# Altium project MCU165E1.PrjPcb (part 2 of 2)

## Sheet MCU165E1_XDS110_MCU.SchDoc
size 431 x 279 mm; Date: Not shown in title block; ApprovedBy: Not shown in title block; CheckedBy: Not shown in title block; Author: Not shown in title block; CompanyName: Not shown in title block; Engineer: Not shown in title block; Organization: Not shown in title block; Address1: Not shown in title block; Address2: Not shown in title block; Address3: Not shown in title block; Address4: Not shown in title block; DocumentNumber: 8; Revision: Use project parameter SCH_Rev; SheetNumber: 8; SheetTotal: 10; PageSetup: Record=PageOptions¦CenterHorizontal=True¦CenterVertical=True¦PrintScale=1.00¦XCorrection=1.00¦YCorrection=1.00¦PrintKind=0¦BorderSize=5000000¦LeftOffset=0¦BottomOffset=0¦Orientation=2¦PaperLength=1000¦PaperWidth=1000¦Scale=100¦PaperSource=15¦PrintQuality=600¦MediaType=1¦DitherType=10¦PaperKind=Letter¦PrintScaleMode=1
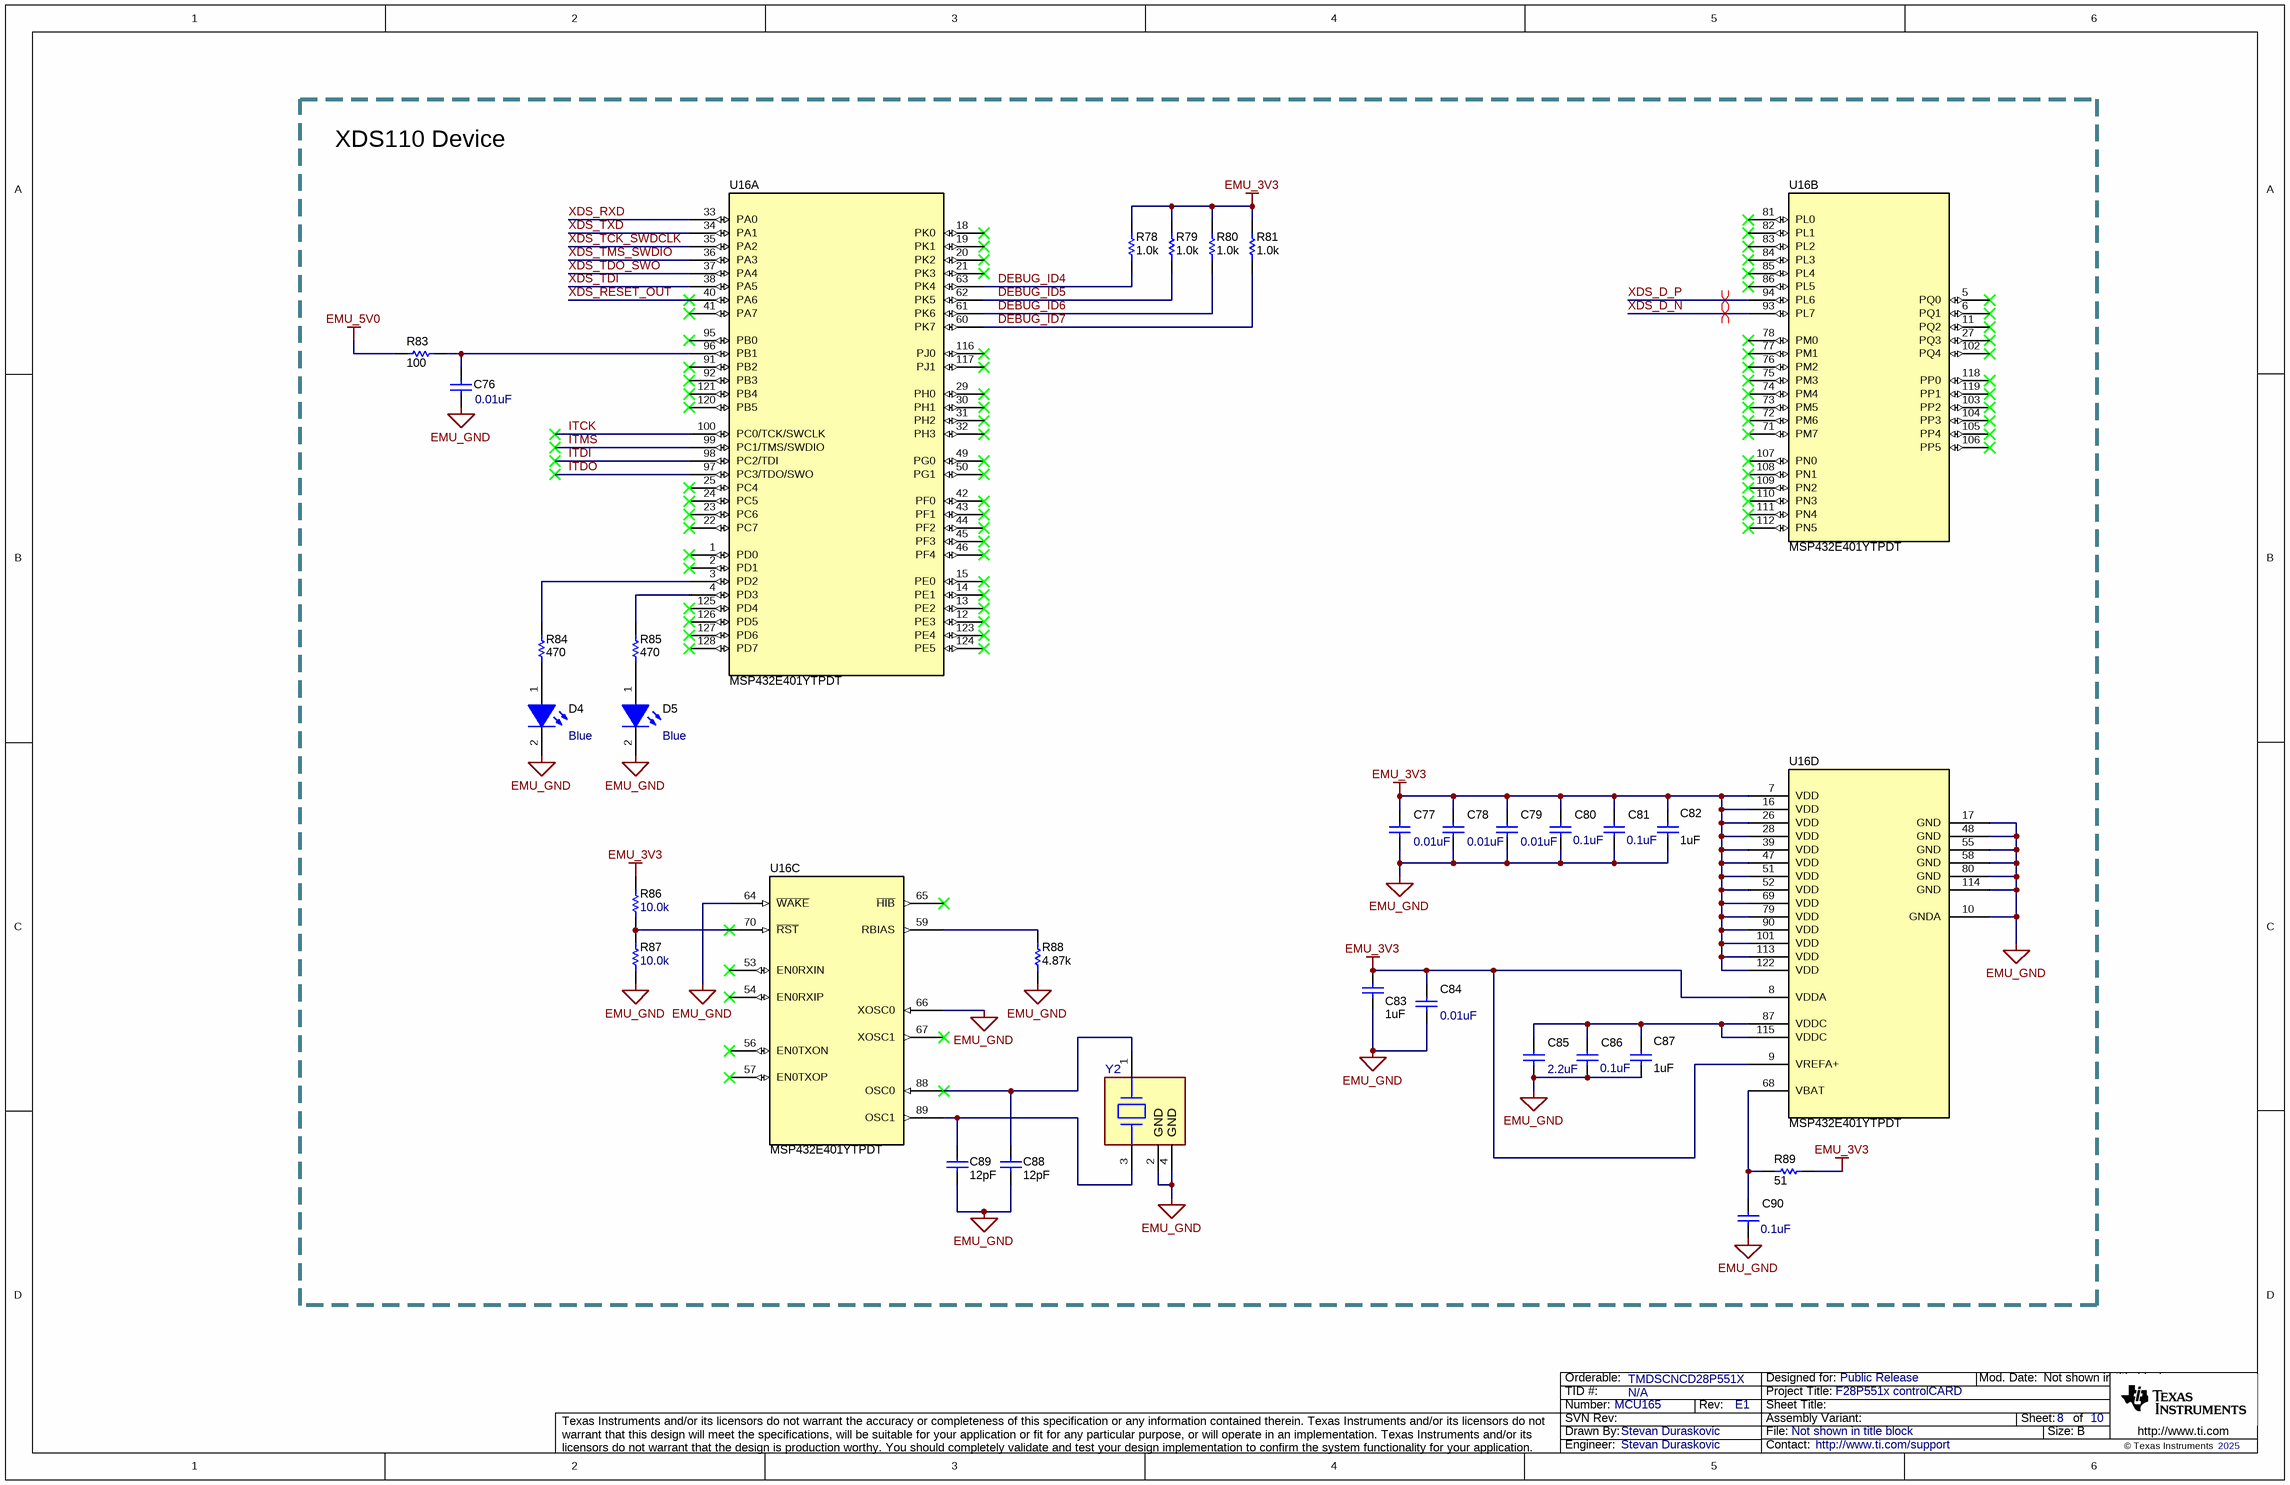
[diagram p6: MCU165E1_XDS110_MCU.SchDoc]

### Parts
C76  ValueDisplayed: 0.01uF  [0402]  (hidden comment: 885012205031)
C77  ValueDisplayed: 0.01uF  [0402]  (hidden comment: 885012205031)
C78  ValueDisplayed: 0.01uF  [0402]  (hidden comment: 885012205031)
C79  ValueDisplayed: 0.01uF  [0402]  (hidden comment: 885012205031)
C80  ValueDisplayed: 0.1uF  [0402]  (hidden comment: 885012205037)
C81  ValueDisplayed: 0.1uF  [0402]  (hidden comment: 885012205037)
C82  ValueDisplayed: 1uF  [0402]  (hidden comment: 885012105012)
C83  ValueDisplayed: 1uF  [0402]  (hidden comment: 885012105012)
C84  ValueDisplayed: 0.01uF  [0402]  (hidden comment: 885012205031)
C85  ValueDisplayed: 2.2uF  [0402]  (hidden comment: 885012105013)
C86  ValueDisplayed: 0.1uF  [0402]  (hidden comment: 885012205037)
C87  ValueDisplayed: 1uF  [0402]  (hidden comment: 885012105012)
C88  ValueDisplayed: 12pF  [0402]  (hidden comment: CL05C120JB5NNNC)
C89  ValueDisplayed: 12pF  [0402]  (hidden comment: CL05C120JB5NNNC)
C90  ValueDisplayed: 0.1uF  [0402]  (hidden comment: 885012205037)
D4  value Blue  [LTST-C170TBKT_Blue]  (hidden comment: LTST-C170TBKT)
D5  value Blue  [LTST-C170TBKT_Blue]  (hidden comment: LTST-C170TBKT)
R78  ValueDisplayed: 1.0k  [0402]  (hidden comment: CRCW04021K00JNED)
R79  ValueDisplayed: 1.0k  [0402]  (hidden comment: CRCW04021K00JNED)
R80  ValueDisplayed: 1.0k  [0402]  (hidden comment: CRCW04021K00JNED)
R81  ValueDisplayed: 1.0k  [0402]  (hidden comment: CRCW04021K00JNED)
R83  ValueDisplayed: 100  [0402]  (hidden comment: CRCW0402100RJNED)
R84  ValueDisplayed: 470  [0402]  (hidden comment: ERJ-2RKF4700X)
R85  ValueDisplayed: 470  [0402]  (hidden comment: ERJ-2RKF4700X)
R86  ValueDisplayed: 10.0k  [0402]  (hidden comment: AC0402FR-0710KL)
R87  ValueDisplayed: 10.0k  [0402]  (hidden comment: AC0402FR-0710KL)
R88  ValueDisplayed: 4.87k  [0402]  (hidden comment: CRCW04024K87FKED)
R89  ValueDisplayed: 51  [0402]  (hidden comment: CRCW040251R0JNED)
U16  MSP432E401YTPDT  [PDT0128A]  (parts A,B,C,D of 4)
Y2  830064296  [FP-830064296_SMT4_3MM4_2MM7-MFG]  (value not drawn)

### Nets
EMU_3V3: C77.1 C78.1 C79.1 C80.1 C81.1 C82.1 C83.1 C84.1 R78.2 R79.2 R80.2 R81.2 R86.2 R89.2 U16.7(VDD) U16.8(VDDA) U16.9(VREFA+) U16.16(VDD) U16.26(VDD) U16.28(VDD) U16.39(VDD) U16.47(VDD) U16.51(VDD) U16.52(VDD) U16.69(VDD) U16.79(VDD) U16.90(VDD) U16.101(VDD) U16.113(VDD) U16.122(VDD)
EMU_5V0: R83.1
EMU_GND: C76.2 C77.2 C78.2 C79.2 C80.2 C81.2 C82.2 C83.2 C84.2 C85.2 C86.2 C87.2 C88.2 C89.2 C90.2 D4.2(K) D5.2(K) R87.1 R88.1 U16.10(GNDA) U16.17(GND) U16.48(GND) U16.55(GND) U16.58(GND) U16.64(~{WAKE}) U16.66(XOSC0) U16.80(GND) U16.114(GND) Y2.2(GND) Y2.4(GND)
DEBUG_ID4: R78.1 U16.63(PK4)
DEBUG_ID5: R79.1 U16.62(PK5)
DEBUG_ID6: R80.1 U16.61(PK6)
DEBUG_ID7: R81.1 U16.60(PK7)
ITCK: U16.100(PC0/TCK/SWCLK)
ITDI: U16.98(PC2/TDI)
ITDO: U16.97(PC3/TDO/SWO)
ITMS: U16.99(PC1/TMS/SWDIO)
XDS_D_N: U16.93(PL7)
XDS_D_P: U16.94(PL6)
XDS_RESET_OUT: U16.40(PA6)
XDS_RXD: U16.33(PA0)
XDS_TCK_SWDCLK: U16.35(PA2)
XDS_TDI: U16.38(PA5)
XDS_TDO_SWO: U16.37(PA4)
XDS_TMS_SWDIO: U16.36(PA3)
XDS_TXD: U16.34(PA1)
NetC76_1: C76.1 R83.2 U16.96(PB1)
NetC85_1: C85.1 C86.1 C87.1 U16.87(VDDC) U16.115(VDDC)
NetC88_1: C88.1 U16.88(OSC0) Y2.1(1_Crystal)
NetC89_1: C89.1 U16.89(OSC1) Y2.3(2_Crystal)
NetC90_1: C90.1 R89.1 U16.68(VBAT)
NetD4_1: D4.1(A) R84.1
NetD5_1: D5.1(A) R85.1
NetR84_2: R84.2 U16.3(PD2)
NetR85_2: R85.2 U16.4(PD3)
NetR86_1: R86.1 R87.2 U16.70(~{RST})
NetR88_2: R88.2 U16.59(RBIAS)

Not connected (* = marked no-connect by the designer): U16 1(PD0)* 2(PD1)* 5(PQ0)* 6(PQ1)* 11(PQ2)* 12(PE3)* 13(PE2)* 14(PE1)* 15(PE0)* 18(PK0)* 19(PK1)* 20(PK2)* 21(PK3)* 22(PC7)* 23(PC6)* 24(PC5)* 25(PC4)* 27(PQ3)* 29(PH0)* 30(PH1)* 31(PH2)* 32(PH3)* 41(PA7)* 42(PF0)* 43(PF1)* 44(PF2)* 45(PF3)* 46(PF4)* 49(PG0)* 50(PG1)* 53(EN0RXIN)* 54(EN0RXIP)* 56(EN0TXON)* 57(EN0TXOP)* 65(~{HIB})* 67(XOSC1)* 71(PM7)* 72(PM6)* 73(PM5)* 74(PM4)* 75(PM3)* 76(PM2)* 77(PM1)* 78(PM0)* 81(PL0)* 82(PL1)* 83(PL2)* 84(PL3)* 85(PL4)* 86(PL5)* 91(PB2)* 92(PB3)* 95(PB0)* 102(PQ4)* 103(PP2)* 104(PP3)* 105(PP4)* 106(PP5)* 107(PN0)* 108(PN1)* 109(PN2)* 110(PN3)* 111(PN4)* 112(PN5)* 116(PJ0)* 117(PJ1)* 118(PP0)* 119(PP1)* 120(PB5)* 121(PB4)* 123(PE4)* 124(PE5)* 125(PD4)* 126(PD5)* 127(PD6)* 128(PD7)*

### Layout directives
differential pair: XDS_D_N, XDS_D_P

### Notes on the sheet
- XDS110 Device

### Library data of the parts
C76-C79 C84 = CMP-0006227-2: CAP, CERM, 0.01 uF, 16 V, +/- 10%, X7R, 0402; Manufacturer: Wurth Elektronik; TaMin_C: -55°C; Polarized: N; SizeAreaWB_mm2: 3; Value1: Unknown; U/M: EA; Value: 0.01uF; TaMax_C: 125°C; SizeZ_mm: 0.6; SizeX_mm: 1; SizeY_mm: 0.5; Value2: 16V; Cap_F: 10nF; AEC Category: Q200
C80 C81 C86 C90 = CMP-0006228-2: CAP, CERM, 0.1 uF, 16 V, +/- 10%, X7R, 0402; Manufacturer: Wurth Elektronik; TaMin_C: -55°C; Polarized: N; SizeAreaWB_mm2: 3; Value1: Unknown; U/M: EA; Value: 0.1uF; TaMax_C: 125°C; SizeZ_mm: 0.6; SizeX_mm: 1; SizeY_mm: 0.5; Value2: 16V; Cap_F: 100nF; AEC Category: Q200
C82 C83 C87 = CMP-0064924-2: CAP, CERM, 1 uF, 10 V,+/- 20%, X5R, 0402; Manufacturer: Wurth Elektronik; TaMin_C: -55°C; Polarized: N; SizeAreaWB_mm2: 3; Value1: Unknown; U/M: EA; Value: 1uF; TaMax_C: 85°C; SizeZ_mm: 0.6; SizeX_mm: 1; SizeY_mm: 0.5; Value2: 10V; Cap_F: 1µF; AEC Category: Q200
C85 = CMP-0006222-2: CAP, CERM, 2.2 uF, 10 V, +/- 20%, X5R, 0402; Manufacturer: Wurth Elektronik; TaMin_C: -55°C; Polarized: N; SizeAreaWB_mm2: 3; Value1: Unknown; U/M: EA; Value: 2.2uF; TaMax_C: 85°C; SizeZ_mm: 0.6; SizeX_mm: 1; SizeY_mm: 0.5; Value2: 10V; Cap_F: 2.2µF; AEC Category: Q200
C88 C89 = CMP-0006345-2: CAP, CERM, 12 pF, 50 V, +/- 5%, C0G/NP0, 0402; Manufacturer: Samsung Electro-Mechanics; Polarized: N; Value: 12pF; U/M: EA; Value1: Unknown; VDC_V: 50V; TaMin_C: -55°C; TaMax_C: 125°C; SizeArea_mm2: 0.5; SizeAreaWB_mm2: 3; SizeX_mm: 1; SizeZ_mm: 0.6; AEC Category: Q200
D4 D5 = CMP-0002889-2: LED, Blue, SMD; Manufacturer: Lite-On; Type: AlInGaP; Vf_V: 3.3V; Io_A: 20mA; Value1: W
R78-R81 = CMP-0026852-3: RES, 1.0 k, 5%, 0.063 W, AEC-Q200 Grade 0, 0402; Manufacturer: Vishay-Dale; Power_W: 63mW; TempCo: 200 ppm/C; Value_Code: 1k00; Value: 1.0k; EIA_Code: E24; Res_ohm: 1k; SizeX_mm: 1; SizeY_mm: 0.5; SizeZ_mm: 0.6; Value2: 0.063W; AEC Qualified: Y; VDC_V: 50V; AEC Category: Q200; AEC Grade: 0
R83 = CMP-0026824-3: RES, 100, 5%, 0.063 W, AEC-Q200 Grade 0, 0402; Manufacturer: Vishay-Dale; Value: 100; Value_Code: 100R; Power_W: 63mW; Value2: 0.063W; VDC_V: 50V; TempCo: 200 ppm/C; SizeArea_mm2: 0.5; SizeX_mm: 1; SizeZ_mm: 0.6; EIA_Code: E24; AEC Category: Q200; AEC Qualified: Y; AEC Grade: 0
R84 R85 = CMP-0026699-1: RES, 470, 1%, 0.1 W, AEC-Q200 Grade 0, 0402; Manufacturer: Panasonic; Value: 470; Value_Code: 470R; Power_W: 100mW; Value2: 0.1W; VDC_V: 50V; TempCo: 100 ppm/C; SizeArea_mm2: 0.5; SizeX_mm: 1; SizeZ_mm: 0.6; U/M: EA; AEC Category: Q200; AEC Qualified: Y; AEC Grade: 0
R86 R87 = CMP-0077731-1: RES, 10.0 k, 1%, 0.063 W, AEC-Q200 Grade 0, 0402; Manufacturer: Yageo America; Power_W: 63mW; TempCo: 100 ppm/C; Value_Code: 10k0; U/M: EA; Value: 10.0k; EIA_Code: E96; Res_ohm: 10k; SizeX_mm: 1.0; SizeY_mm: 0.5; SizeZ_mm: 0.6; Value2: 0.063W; AEC Qualified: Y; VDC_V: 50V; AEC Grade: 0; AEC Category: Q200
R88 = CMP-0026413-2: RES, 4.87 k, 1%, 0.063 W, AEC-Q200 Grade 0, 0402; Manufacturer: Vishay-Dale; Value: 4.87k; Value_Code: 4k87; Power_W: 63mW; Value2: 0.063W; VDC_V: 50V; TempCo: 100 ppm/C; SizeArea_mm2: 0.5; SizeX_mm: 1; SizeZ_mm: 0.6; EIA_Code: E96; AEC Category: Q200; AEC Qualified: Y; AEC Grade: 0
R89 = CMP-0026946-3: RES, 51, 5%, 0.063 W, AEC-Q200 Grade 0, 0402; Manufacturer: Vishay-Dale; Value: 51; Value_Code: 51R0; Power_W: 63mW; Value2: 0.063W; VDC_V: 50V; TempCo: 200 ppm/C; SizeArea_mm2: 0.5; SizeX_mm: 1; SizeZ_mm: 0.6; EIA_Code: E24; AEC Category: Q200; AEC Qualified: Y; AEC Grade: 0
U16 = CMP-0077953-1: MSP432E401YTPDT, PDT0128A (TQFP-128); Alternate PartNumber: MSP432E401YTPDTR; Alternate Manufacturer: Texas Instruments; SizeAreaWB_mm2: 324; SizeZ_mm: 1.2; SizeX_mm: 16; SizeArea_mm2: 256; CompType: IC; AEC Qualified: N; AEC Category: Q200
Y2 = CMP-0094478-1: Crystal 16 MHz ±20ppm Crystal 8pF 70 Ohms 4-SMD, No Lead; Manufacturer: Wurth; SizeZ_mm: 0.8mm; Frequency_Fixed: 16MHz; Esr: 70

## Sheet MCU165E1_Emulator_Interface.SchDoc
size 431 x 279 mm; Date: Not shown in title block; ApprovedBy: Not shown in title block; CheckedBy: Not shown in title block; Author: Not shown in title block; CompanyName: Not shown in title block; Engineer: Not shown in title block; Organization: Not shown in title block; Address1: Not shown in title block; Address2: Not shown in title block; Address3: Not shown in title block; Address4: Not shown in title block; DocumentNumber: 9; Revision: Use project parameter SCH_Rev; SheetNumber: 9; SheetTotal: 10; PageSetup: Record=PageOptions¦CenterHorizontal=True¦CenterVertical=True¦PrintScale=1.00¦XCorrection=1.00¦YCorrection=1.00¦PrintKind=0¦BorderSize=5000000¦LeftOffset=0¦BottomOffset=0¦Orientation=2¦PaperLength=1000¦PaperWidth=1000¦Scale=100¦PaperSource=15¦PrintQuality=600¦MediaType=1¦DitherType=10¦PaperKind=Letter¦PrintScaleMode=1
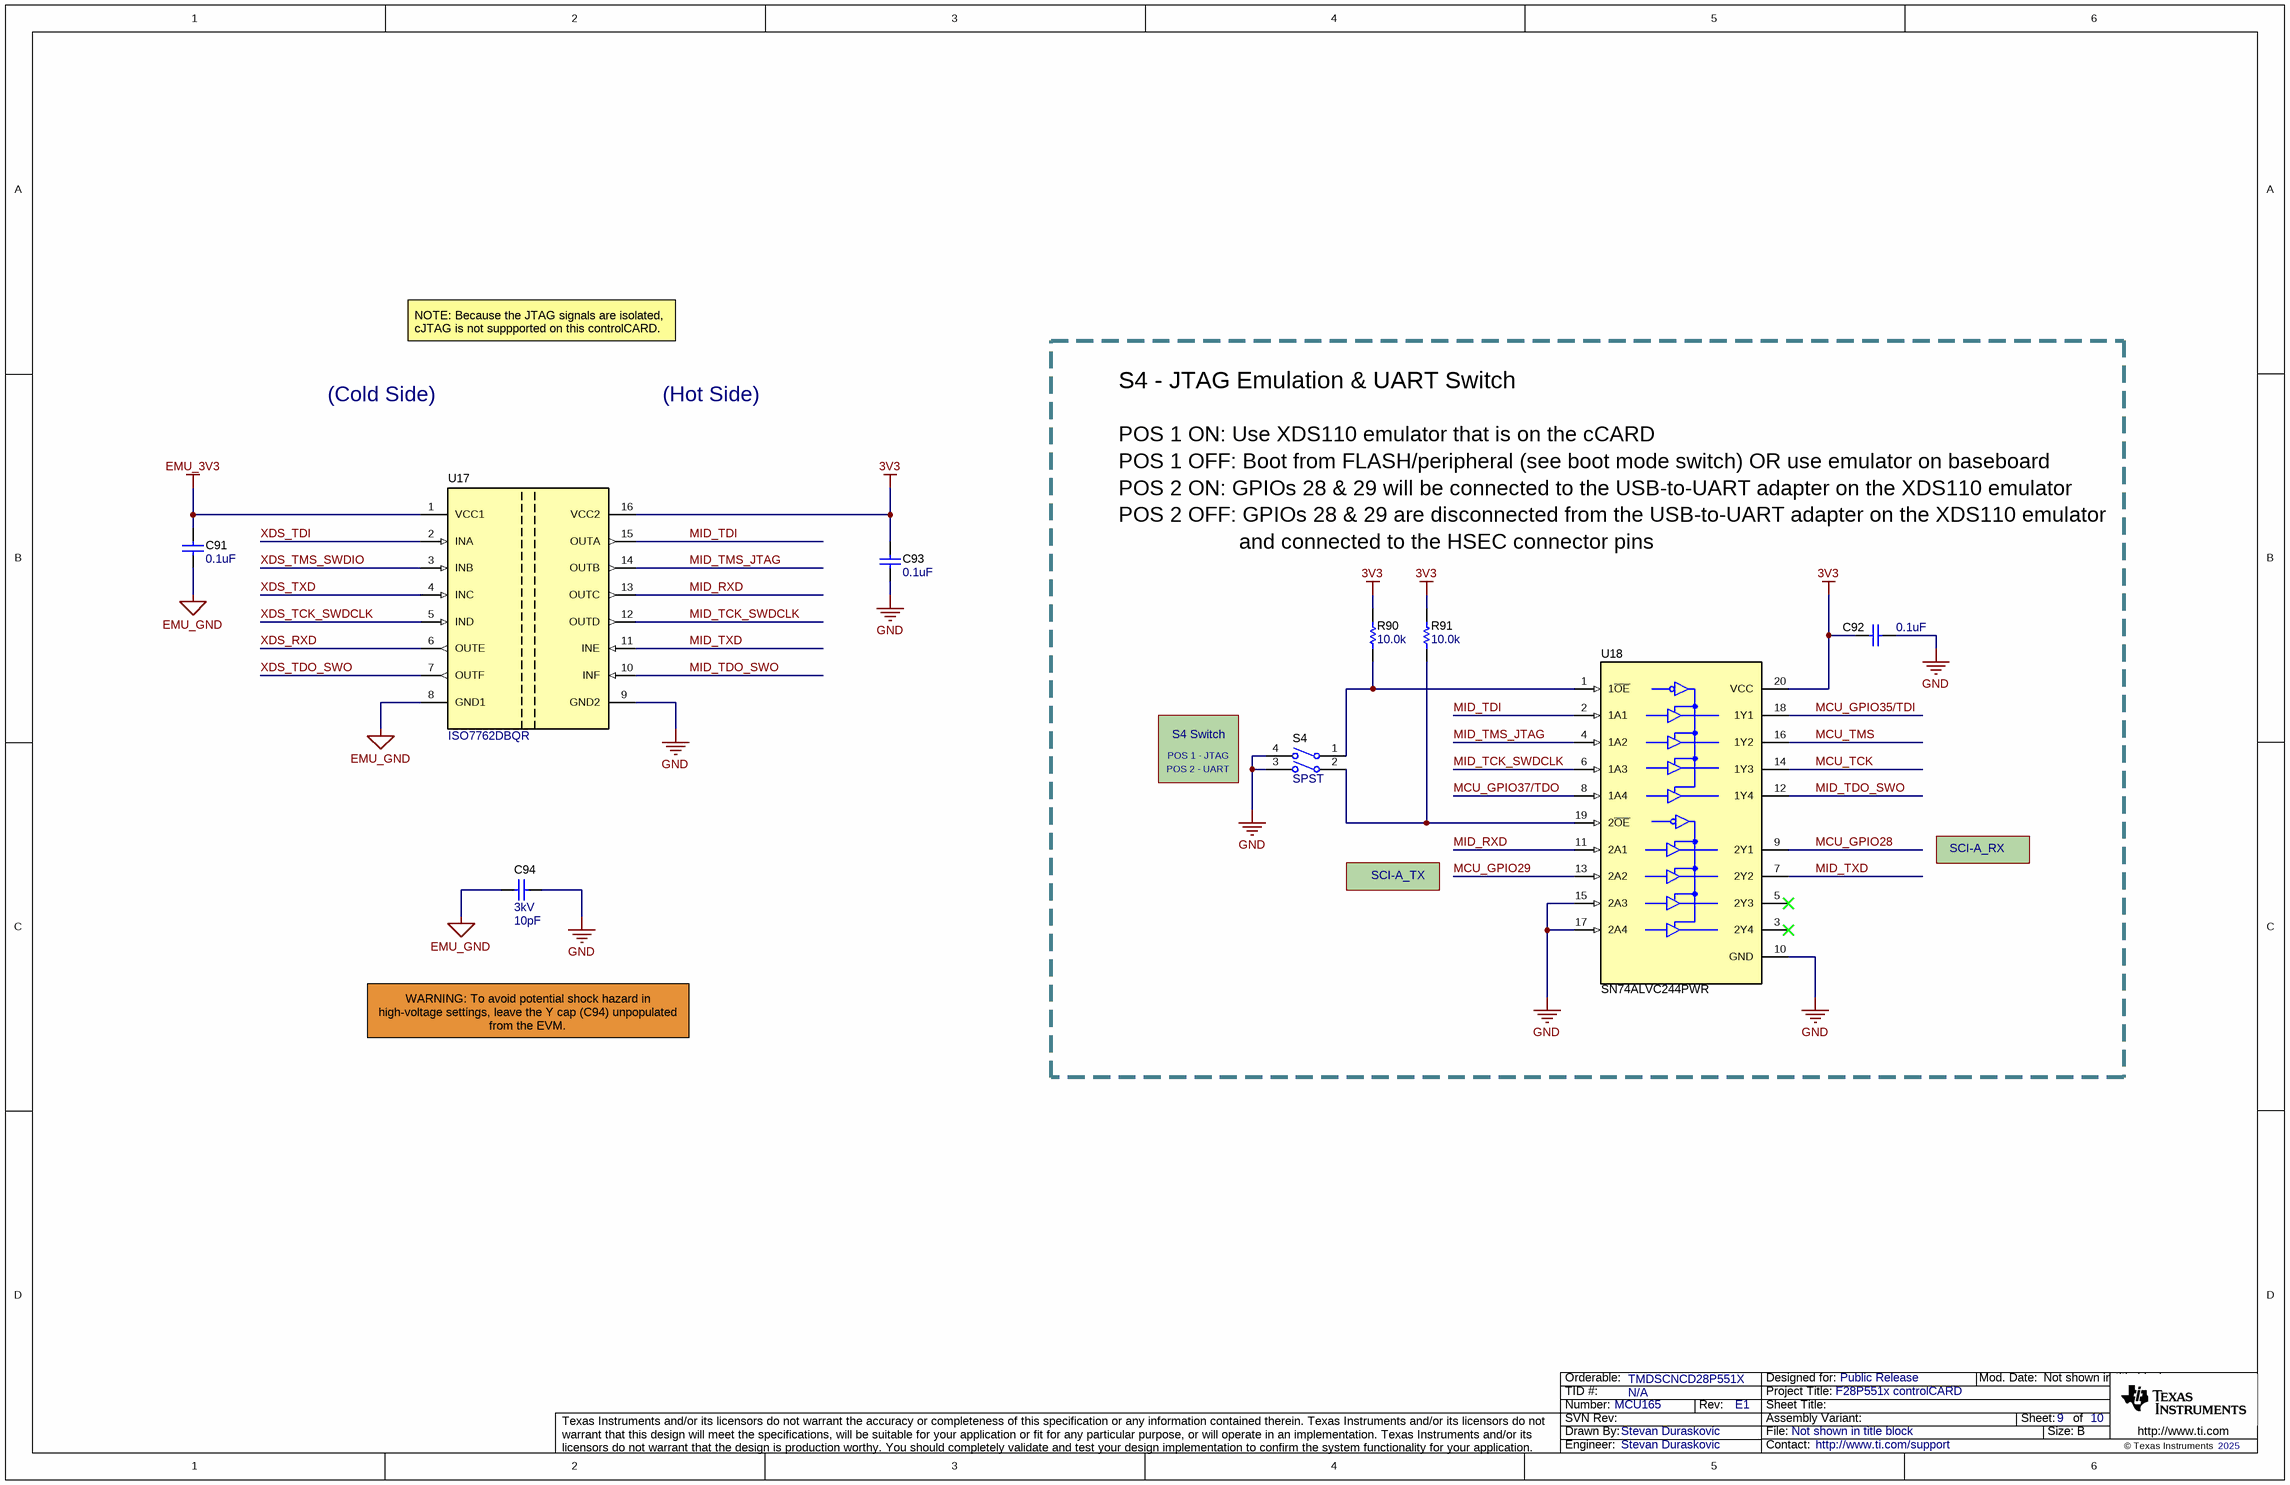
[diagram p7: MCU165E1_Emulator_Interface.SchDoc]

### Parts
C91  ValueDisplayed: 0.1uF  [0402]  (hidden comment: 885012205037)
C92  ValueDisplayed: 0.1uF  [0402]  (hidden comment: 885012205037)
C93  ValueDisplayed: 0.1uF  [0402]  (hidden comment: 885012205037)
C94  VDC_V: 3kV  ValueDisplayed: 10pF  [1812_180]  (hidden comment: C1812C100JHGACTU)
R90  ValueDisplayed: 10.0k  [0402]  (hidden comment: AC0402FR-0710KL)
R91  ValueDisplayed: 10.0k  [0402]  (hidden comment: AC0402FR-0710KL)
S4  Circuit: SPST  [SW_218-2LP]  (hidden comment: 218-2LPST)
U17  ISO7762DBQR  [DBQ0016A_N]
U18  SN74ALVC244PWR  [PW0020A_N]

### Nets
3V3: C92.2 C93.1 R90.2 R91.2 U17.16(VCC2) U18.20(VCC)
EMU_3V3: C91.1 U17.1(VCC1)
EMU_GND: C91.2 C94.2 U17.8(GND1)
GND: C92.1 C93.2 C94.1 S4.3 S4.4 U17.9(GND2) U18.10(GND) U18.15(2A3) U18.17(2A4)
MCU_GPIO28: U18.9(2Y1)
MCU_GPIO29: U18.13(2A2)
MCU_GPIO35/TDI: U18.18(1Y1)
MCU_GPIO37/TDO: U18.8(1A4)
MCU_TCK: U18.14(1Y3)
MCU_TMS: U18.16(1Y2)
MID_RXD: U17.13(OUTC) U18.11(2A1)
MID_TCK_SWDCLK: U17.12(OUTD) U18.6(1A3)
MID_TDI: U17.15(OUTA) U18.2(1A1)
MID_TDO_SWO: U17.10(INF) U18.12(1Y4)
MID_TMS_JTAG: U17.14(OUTB) U18.4(1A2)
MID_TXD: U17.11(INE) U18.7(2Y2)
XDS_RXD: U17.6(OUTE)
XDS_TCK_SWDCLK: U17.5(IND)
XDS_TDI: U17.2(INA)
XDS_TDO_SWO: U17.7(OUTF)
XDS_TMS_SWDIO: U17.3(INB)
XDS_TXD: U17.4(INC)
NetR90_1: R90.1 S4.1 U18.1(1~{OE})
NetR91_1: R91.1 S4.2 U18.19(2~{OE})

Not connected (* = marked no-connect by the designer): U18 3(2Y4)* 5(2Y3)*

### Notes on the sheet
- NOTE: Because the JTAG signals are isolated, cJTAG is not suppported on this controlCARD.
- (Cold Side)
- (Hot Side)
- S4 - JTAG Emulation & UART Switch
- POS 1 ON: Use XDS110 emulator that is on the cCARD
- POS 1 OFF: Boot from FLASH/peripheral (see boot mode switch) OR use emulator on baseboard
- POS 2 ON: GPIOs 28 & 29 will be connected to the USB-to-UART adapter on the XDS110 emulator
- POS 2 OFF: GPIOs 28 & 29 are disconnected from the USB-to-UART adapter on the XDS110 emulator
- and connected to the HSEC connector pins
- S4 Switch
- POS 1 - JTAG
- POS 2 - UART
- SCI-A_TX
- SCI-A_RX
- WARNING: To avoid potential shock hazard in high-voltage settings, leave the Y cap (C94) unpopulated from the EVM.

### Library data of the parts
C91-C93 = CMP-0006228-2: as C80 on sheet MCU165E1_XDS110_MCU
C94 = CMP-0082066-1: CAP, CERM, 10 pF, 3000 V,+/- 5%, C0G/NP0, AEC-Q200 Grade 1, 1812; Manufacturer: Kemet; SizeAreaWB_mm2: 23.1; SizeArea_mm2: 14.4; AEC Qualified: Y; AEC Category: Q200; Value: 10pF; TaMax_C: 125°C; SizeZ_mm: 1.8; AEC Grade: 1; Polarized: N; TaMin_C: -55°C; SizeY_mm: 3.2; Value2: 3000V; U/M: EA; SizeX_mm: 4.5; Cap_Case: 1812
R90 R91 = CMP-0077731-1: as R86 on sheet MCU165E1_XDS110_MCU
S4 = CMP-0002230-1: Switch, SPST, 2 Pos, 25mA, 24VDC, SMD; Manufacturer: CTS Electrocomponents; VDC_V: 24V; SwitchFunction: Off-On; PositionCount: 2; CurrentRating_mA: 25A
U17 = CMP-0067607-3: High Speed, Robust EMC, Reinforced Six-Channel Digital Isolator, DBQ0016A (SSOP-16); Manufacturer: Texas Instruments; SizeX_mm: 6.0; SizeY_mm: 10.0; CompType: IC; SizeZ_mm: 1.75; SizeArea_mm2: 60.0; SizeAreaWB_mm2: 96.0; U/M: EA; AEC Category: Q200; AEC Qualified: N
U18 = CMP-0047070-3: Octal Buffer/Driver With 3-State OUtputs, PW0020A (TSSOP-20); Manufacturer: Texas Instruments; Bits(#): 8; F @ Nom Voltage(Max)(Mhz): 100; ICC @ Nom Voltage(Max)(mA): 0.024; Input Type: LVTTL; Rating: Catalog; tpd @ Nom Voltage(Max)(ns): 4.4,3.1,2.8; VCC(Max)(V): 3.6; VCC(Min)(V): 1.65; Voltage(Nom)(V): 1.8,2.5,2.7,3.3; AEC Category: Q200; AEC Qualified: N; CompType: IC; SizeArea_mm2: 43.56; SizeAreaWB_mm2: 73.96; SizeX_mm: 6.6; SizeZ_mm: 1.2

## Sheet MCU165E1_Hardware.SchDoc
size 431 x 279 mm; Date: Not shown in title block; ApprovedBy: Not shown in title block; CheckedBy: Not shown in title block; Author: Not shown in title block; CompanyName: Not shown in title block; Engineer: Not shown in title block; Organization: Not shown in title block; Address1: Not shown in title block; Address2: Not shown in title block; Address3: Not shown in title block; Address4: Not shown in title block; DocumentNumber: 10; Revision: Use project parameter SCH_Rev; SheetNumber: 10; SheetTotal: 10; PageSetup: Record=PageOptions¦CenterHorizontal=True¦CenterVertical=True¦PrintScale=1.00¦XCorrection=1.00¦YCorrection=1.00¦PrintKind=0¦BorderSize=5000000¦LeftOffset=0¦BottomOffset=0¦Orientation=2¦PaperLength=1000¦PaperWidth=1000¦Scale=100¦PaperSource=15¦PrintQuality=600¦MediaType=1¦DitherType=10¦PaperKind=Letter¦PrintScaleMode=1
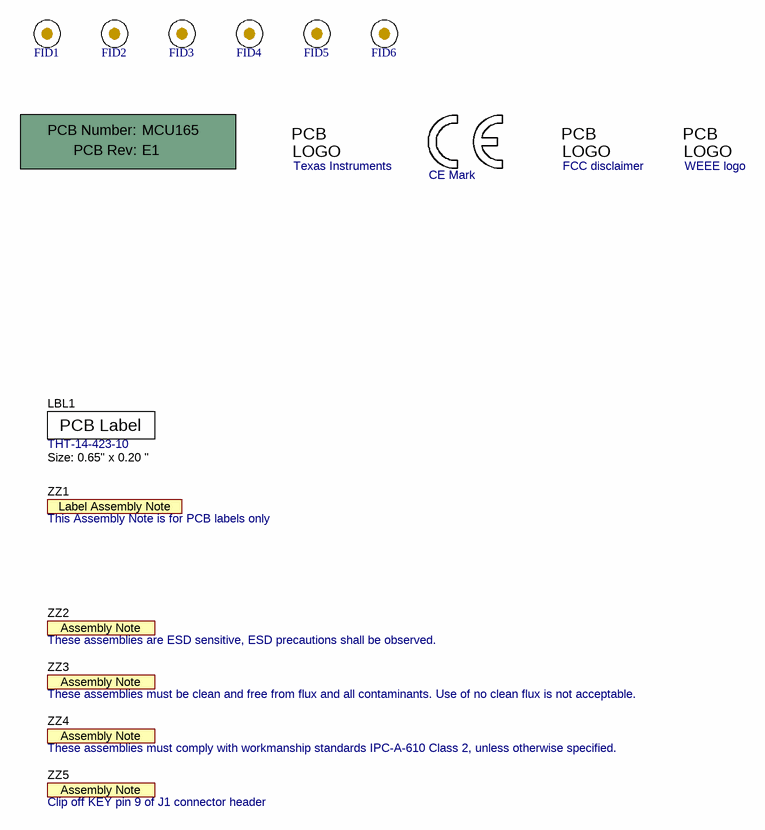
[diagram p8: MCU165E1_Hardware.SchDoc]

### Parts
!PCB1  Printed Circuit Board  (value not drawn)  (mechanical)
FID1  Fiducial  [Fiducial10-20]  (value not drawn)
FID2  Fiducial  [Fiducial10-20]  (value not drawn)
FID3  Fiducial  [Fiducial10-20]  (value not drawn)
FID4  Fiducial  [Fiducial10-20]  (value not drawn)
FID5  Fiducial  [Fiducial10-20]  (value not drawn)
FID6  Fiducial  [Fiducial10-20]  (value not drawn)
LBL1  THT-14-423-10  Note: Size: 0.65" x 0.20 "  [Label_650x200]
Logo1  CE Mark  [CE_Mark_5mm]  (no BOM)
Logo2  Texas Instruments  [TI_Stacked_Overlay_Small]  (no BOM)
Logo3  FCC disclaimer  [FCC_disclaimer]  (no BOM)
Logo4  WEEE logo  [WEEE_Minimum]  (no BOM)
ZZ1  This Assembly Note is for PCB labels only  [AssemblyNoteLabel]  (no BOM)
ZZ2  These assemblies are ESD sensitive, ESD precautions shall be observed.  [AssemblyNote]  (no BOM)
ZZ3  These assemblies must be clean and free from flux and all contaminants. Use of no clean flux is not acceptable.  [AssemblyNote]  (no BOM)
ZZ4  These assemblies must comply with workmanship standards IPC-A-610 Class 2, unless otherwise specified.  [AssemblyNote]  (no BOM)
ZZ5  Clip off KEY pin 9 of J1 connector header  [AssemblyNote]  (no BOM)

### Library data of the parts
!PCB1 = CMP-0003618-2: Manufacturer: Any; PartNumber: MCU165
FID1-FID6 = CMP-0077181-1: Fiducial mark.  There is nothing to buy or mount.
LBL1 = CMP-0003625-1: Thermal Transfer Printable Labels, 0.650" W x 0.200" H - 10,000 per roll; Manufacturer: Brady
Logo1 = CMP-0074844-1: SymbolCreator: a0412235
Logo2 = CMP-0074838-1: Texas Instrument Corporate Signature; SymbolCreator: a0412235; Lib Reference: TI_Logo
Logo3 = CMP-0074847-1: FCC_disclaimer
Logo4 = CMP-0074769-1
ZZ1 = CMP-0003616-3
ZZ2 = CMP-0077236-1
ZZ3 = CMP-0077237-1
ZZ4 ZZ5 = CMP-0077238-1

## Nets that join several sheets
3V3: MCU165E1_GPIO (EC1.119 J1.10 R1.1 R2.2), MCU165E1_Support (14 pins), MCU165E1_Power (6 pins), MCU165E1_Emulator_Interface (6 pins)
5V0: MCU165E1_Support (C4.1 U2.2), MCU165E1_Power (C7.1 U4.4 U4.6), MCU165E1_XDS110_USB_Power (R67.1 R71.2 TP11.1)
EMU_3V3: MCU165E1_XDS110_USB_Power (C73.2 R76.1 TP8.1 U15.5), MCU165E1_XDS110_MCU (30 pins), MCU165E1_Emulator_Interface (C91.1 U17.1)
EMU_5V0: MCU165E1_XDS110_USB_Power (16 pins), MCU165E1_XDS110_MCU (R83.1)
EMU_GND: MCU165E1_XDS110_USB_Power (27 pins), MCU165E1_XDS110_MCU (30 pins), MCU165E1_Emulator_Interface (C91.2 C94.2 U17.8)
GND: MCU165E1_GPIO (14 pins), MCU165E1_Support (16 pins), MCU165E1_Power (23 pins), MCU165E1_ADC (36 pins), MCU165E1_XDS110_USB_Power (16 pins), MCU165E1_Emulator_Interface (9 pins)
HSEC_5V0: MCU165E1_GPIO (EC1.48 EC1.84 EC1.98 EC1.112), MCU165E1_Power (TP2.1), MCU165E1_XDS110_USB_Power (5 pins)
VDD_1V2: MCU165E1_GPIO (EC1.118), MCU165E1_Power (8 pins)
VDDA_3V3: MCU165E1_Power (C12.1 L1.2 TP4.1 U1.34), MCU165E1_ADC (10 pins)
HSEC_A0/B15/C15/DACA_OUT: MCU165E1_GPIO (EC1.9), MCU165E1_ADC (R26.2 U5.2)
HSEC_A1/B7/D11/DACB_OUT: MCU165E1_GPIO (EC1.11), MCU165E1_ADC (R27.2 U5.1)
HSEC_A3/B9/C7: MCU165E1_GPIO (EC1.39), MCU165E1_ADC (R29.2 U8.6)
HSEC_A4/B8: MCU165E1_GPIO (EC1.17), MCU165E1_ADC (R30.2 U7.1)
HSEC_A5: MCU165E1_GPIO (EC1.28), MCU165E1_ADC (R31.2 U9.3)
HSEC_A6/D14/E14: MCU165E1_GPIO (EC1.23), MCU165E1_ADC (R32.2 U6.6)
HSEC_A7/B30/C3/D12/E30: MCU165E1_GPIO (EC1.33), MCU165E1_ADC (R33.2 U8.1)
HSEC_A8: MCU165E1_GPIO (EC1.30), MCU165E1_ADC (R34.2 U9.7)
HSEC_A9: MCU165E1_GPIO (EC1.34), MCU165E1_ADC (R35.2 U9.6)
HSEC_A10/B1/C10: MCU165E1_GPIO (EC1.25), MCU165E1_ADC (R36.2 U9.2)
HSEC_A11/B10/C0/PGA2_OUT: MCU165E1_GPIO (EC1.27), MCU165E1_ADC (R37.2 U9.1)
HSEC_A12/C5: MCU165E1_GPIO (EC1.37), MCU165E1_ADC (R38.2 U8.7)
HSEC_A14/B14/C4/PGA1_OUT: MCU165E1_GPIO (EC1.36), MCU165E1_ADC (R39.2 U8.3)
HSEC_B0/C11: MCU165E1_GPIO (EC1.31), MCU165E1_ADC (R41.2 U8.2)
HSEC_B2/C6/E12: MCU165E1_GPIO (EC1.14), MCU165E1_ADC (R42.2 U5.6)
HSEC_B4/C8: MCU165E1_GPIO (EC1.20), MCU165E1_ADC (R40.2 U6.1)
HSEC_B5/D15/E15/PGA3_OUT: MCU165E1_GPIO (EC1.26), MCU165E1_ADC (R44.2 U6.7)
HSEC_B11/D16/E16: MCU165E1_GPIO (EC1.24), MCU165E1_ADC (R45.2 U6.8)
HSEC_B12/C2: MCU165E1_GPIO (EC1.12), MCU165E1_ADC (R46.2 U5.3)
HSEC_C14: MCU165E1_GPIO (EC1.40), MCU165E1_ADC (R49.2 U8.8)
HSEC_GPIO18: MCU165E1_GPIO (EC1.71), MCU165E1_Support (S5.3)
HSEC_GPIO19: MCU165E1_GPIO (EC1.73), MCU165E1_Support (S5.6)
HSEC_PGA1_IN_N: MCU165E1_GPIO (EC1.13), MCU165E1_ADC (R94.2 U5.8)
HSEC_PGA1_IN_P: MCU165E1_GPIO (EC1.15), MCU165E1_ADC (R28.2 U5.7)
HSEC_PGA2_IN_N: MCU165E1_GPIO (EC1.19), MCU165E1_ADC (R95.2 U6.3)
HSEC_PGA2_IN_P: MCU165E1_GPIO (EC1.21), MCU165E1_ADC (R43.2 U6.2)
HSEC_PGA3_IN_N: MCU165E1_GPIO (EC1.16), MCU165E1_ADC (R96.2 U7.3)
HSEC_PGA3_IN_P: MCU165E1_GPIO (EC1.18), MCU165E1_ADC (R48.2 U7.4)
HSEC_VREFHIABCDE: MCU165E1_GPIO (EC1.45), MCU165E1_ADC (S3.2)
MCU_GPIO24: MCU165E1_GPIO (EC1.75 U1.56), MCU165E1_Support (R9.2)
MCU_GPIO28: MCU165E1_GPIO (EC1.76 U1.1), MCU165E1_Emulator_Interface (U18.9)
MCU_GPIO29: MCU165E1_GPIO (EC1.78 U1.100), MCU165E1_Emulator_Interface (U18.13)
MCU_GPIO31: MCU165E1_GPIO (EC1.82 U1.99), MCU165E1_Support (R21.1 U3.1)
MCU_GPIO32: MCU165E1_GPIO (EC1.85 U1.64), MCU165E1_Support (R10.1)
MCU_GPIO34: MCU165E1_GPIO (EC1.86 U1.94), MCU165E1_Support (R22.1 U3.3)
MCU_GPIO35/TDI: MCU165E1_GPIO (EC1.8), MCU165E1_Support (R11.1 U1.63), MCU165E1_Emulator_Interface (U18.18)
MCU_GPIO37/TDO: MCU165E1_GPIO (EC1.6), MCU165E1_Support (R12.1 U1.61), MCU165E1_Emulator_Interface (U18.8)
MCU_TCK: MCU165E1_GPIO (EC1.5), MCU165E1_Support (U1.60), MCU165E1_Emulator_Interface (U18.14)
MCU_TMS: MCU165E1_GPIO (EC1.3), MCU165E1_Support (R13.1 U1.62), MCU165E1_Emulator_Interface (U18.16)
MCU_XRSn: MCU165E1_GPIO (EC1.120), MCU165E1_Support (6 pins)
XDS_D_N: MCU165E1_XDS110_USB_Power (J3.A7 J3.B7 U13.2 U13.9), MCU165E1_XDS110_MCU (U16.93)
XDS_D_P: MCU165E1_XDS110_USB_Power (J3.A6 J3.B6 U13.1 U13.10), MCU165E1_XDS110_MCU (U16.94)
XDS_RXD: MCU165E1_XDS110_MCU (U16.33), MCU165E1_Emulator_Interface (U17.6)
XDS_TCK_SWDCLK: MCU165E1_XDS110_MCU (U16.35), MCU165E1_Emulator_Interface (U17.5)
XDS_TDI: MCU165E1_XDS110_MCU (U16.38), MCU165E1_Emulator_Interface (U17.2)
XDS_TDO_SWO: MCU165E1_XDS110_MCU (U16.37), MCU165E1_Emulator_Interface (U17.7)
XDS_TMS_SWDIO: MCU165E1_XDS110_MCU (U16.36), MCU165E1_Emulator_Interface (U17.3)
XDS_TXD: MCU165E1_XDS110_MCU (U16.34), MCU165E1_Emulator_Interface (U17.4)

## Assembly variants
001: not fitted C29 C30 C31 C32 C33 C34 C35 C36 C37 C38 C39 C40 C41 C42 C43 C44 C45 C46 C47 C48 C49 C51 C52 C62 C94 C96 C96 C97 C97 C98 C98 FID1 FID2 FID3 FID4 FID5 FID6 R16 R62 R87 R94 R95 R?
F28P551x-Required-Circuitry-Only: all parts fitted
